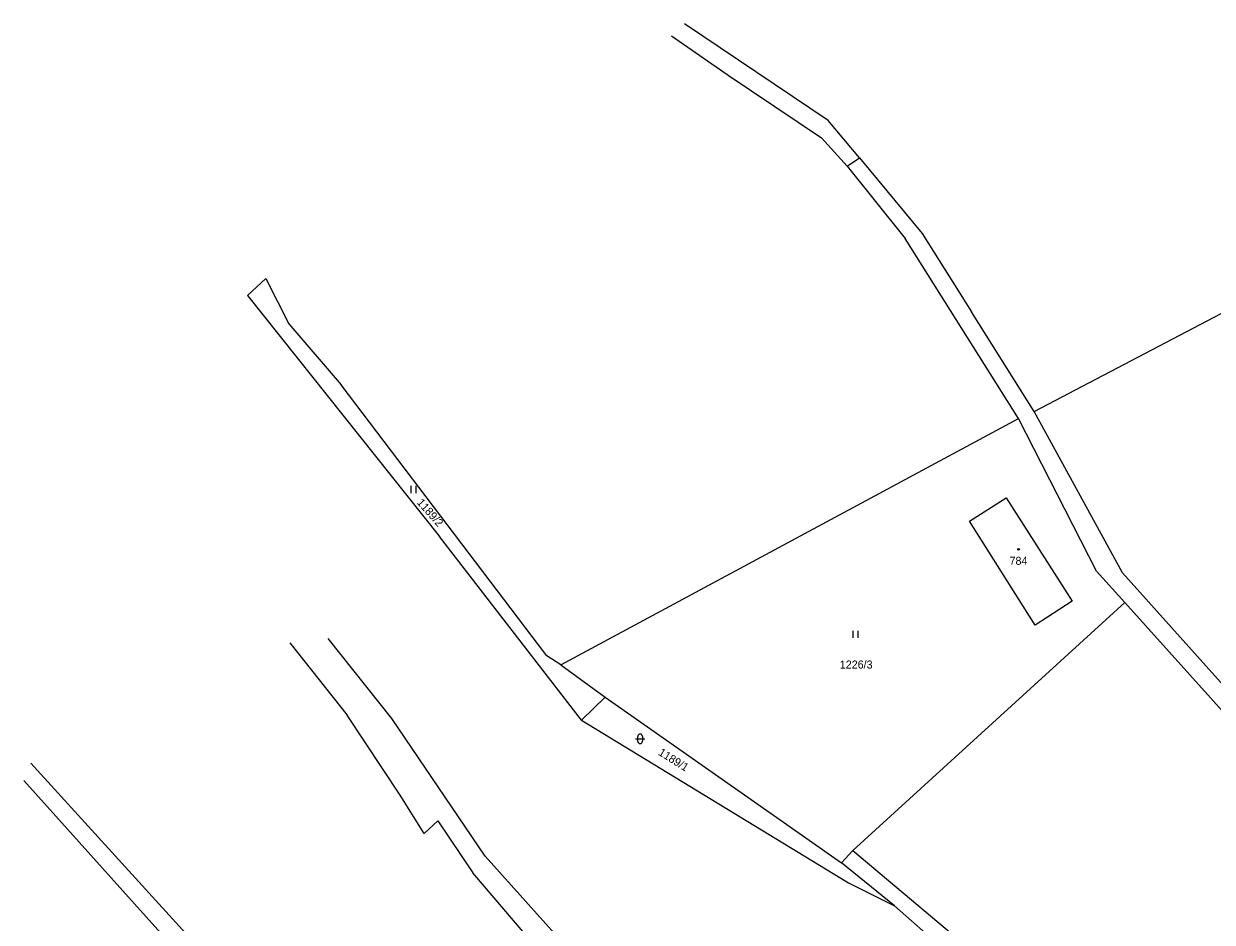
# Model space of a CAD drawing. Extents: x -717507 to -715515, y -957700 to -954941.
# Drawn here: x -717381.9 to -717129.5, y -956944.1 to -956753.3 of the extents above; entities that cross this region are included whole.
import ezdxf

# ---------------------------------------------------------------- set-up
doc = ezdxf.new("R2010")
doc.units = 0
for name, color, linetype in [('Hranice parcel', 7, 'Continuous'), ('Parcelní čísla', 7, 'Continuous'), ('Značky budov', 7, 'Continuous'), ('Značky kultur', 7, 'Continuous')]:
    doc.layers.add(name, color=color, linetype=linetype)

msp = doc.modelspace()

# ---------------------------------------------------------------- linework, layer by layer
at = {"layer": 'Hranice parcel'}
for points in [[(-717211.1, -956773.89), (-717241.62, -956753.35)], [(-717244.34, -956755.94), (-717232.28, -956764.24)], [(-717232.28, -956764.24), (-717212.52, -956777.58)], [(-717204.42, -956781.8), (-717211.1, -956773.89)], [(-717207.02, -956783.61), (-717212.52, -956777.58)], [(-717207.02, -956783.61), (-717204.42, -956781.8)], [(-717204.42, -956781.8), (-717191.14, -956797.87)], [(-717207.02, -956783.61), (-717194.73, -956798.97)], [(-717170.69, -956837.15), (-717194.73, -956798.97)], [(-717191.14, -956797.87), (-717180.67, -956814.53)], [(-717330.49, -956807.41), (-717334.37, -956811.04)], [(-717330.49, -956807.41), (-717325.62, -956817.07)], [(-717334.37, -956811.04), (-717293.61, -956862.18)], [(-717167.3, -956835.66), (-717180.67, -956814.53)], [(-717167.3, -956835.66), (-717126.11, -956814.08)], [(-717325.62, -956817.07), (-717314.48, -956830.03)], [(-717270.8, -956887.52), (-717314.48, -956830.03)], [(-717148.57, -956869.93), (-717167.3, -956835.66)], [(-717267.82, -956889.47), (-717170.69, -956837.15)], [(-717154.08, -956869.54), (-717170.69, -956837.15)], [(-717181.08, -956858.97), (-717173.31, -956854)], [(-717173.31, -956854), (-717159.27, -956875.97)], [(-717167.11, -956881.07), (-717181.08, -956858.97)], [(-717263.48, -956901.2), (-717293.61, -956862.18)], [(-717148.05, -956876.22), (-717154.08, -956869.54)], [(-717097.11, -956927.29), (-717148.57, -956869.93)], [(-717159.27, -956875.97), (-717167.11, -956881.07)], [(-717148.05, -956876.22), (-717205.81, -956928.88)], [(-717101.64, -956927.88), (-717148.05, -956876.22)], [(-717325.42, -956884.81), (-717313.2, -956900.16)], [(-717303.74, -956900.85), (-717317.24, -956883.9)], [(-717267.82, -956889.47), (-717270.8, -956887.52)], [(-717267.82, -956889.47), (-717258.42, -956896.34)], [(-717263.48, -956901.2), (-717258.42, -956896.34)], [(-717258.42, -956896.34), (-717208.27, -956931.47)], [(-717301.99, -956917.13), (-717313.2, -956900.16)], [(-717283.89, -956930.09), (-717303.74, -956900.85)], [(-717263.48, -956901.2), (-717206.78, -956935.75)], [(-717343.19, -956951.26), (-717380.43, -956910.35)], [(-717344.17, -956956.03), (-717381.9, -956914.02)], [(-717296.84, -956925.24), (-717301.99, -956917.13)], [(-717296.84, -956925.24), (-717293.97, -956922.59)], [(-717293.97, -956922.59), (-717286.54, -956933.65)], [(-717205.81, -956928.88), (-717208.27, -956931.47)], [(-717205.81, -956928.88), (-717176.91, -956953.25)], [(-717265.49, -956950.61), (-717283.89, -956930.09)], [(-717197, -956940.61), (-717208.27, -956931.47)], [(-717269.66, -956953.34), (-717286.54, -956933.65)], [(-717206.78, -956935.75), (-717197, -956940.61)], [(-717175.29, -956959.79), (-717197, -956940.61)]]:
    msp.add_lwpolyline(points, dxfattribs=at)
at = {"layer": 'Značky budov'}
msp.add_circle((-717170.65, -956864.94), 0.175, dxfattribs=at)
at = {"layer": 'Značky kultur'}
for points in [[(-717299.64, -956852.98), (-717299.64, -956851.48)], [(-717298.6, -956852.98), (-717298.6, -956851.48)], [(-717205.77, -956883.72), (-717205.77, -956882.22)], [(-717204.73, -956883.72), (-717204.73, -956882.22)], [(-717252.01, -956905.17), (-717250.01, -956905.17)], [(-717251.51, -956905.67), (-717251.51, -956904.67)], [(-717250.51, -956904.67), (-717250.51, -956905.67)]]:
    msp.add_lwpolyline(points, dxfattribs=at)
for centre, start, end in [((-717251.01, -956904.67), 0.101, 180.0014), ((-717251.01, -956905.67), 180.1024, 0.0029)]:
    msp.add_arc(centre, 0.5, start, end, dxfattribs=at)

# ---------------------------------------------------------------- texts
at = {"layer": 'Parcelní čísla'}
for s, rotation, p in [('1189/2', 311.5025, (-717298.53, -956855.08)), ('1189/1', 328.1026, (-717247.29, -956908.48))]:
    msp.add_text(s, height=1.7, rotation=rotation, dxfattribs=at).set_placement(p)
for s, p in [('784', (-717172.56, -956868.22)), ('1226/3', (-717208.61, -956890.24))]:
    msp.add_text(s, height=1.7, dxfattribs=at).set_placement(p)

doc.saveas('drawing.dxf')
